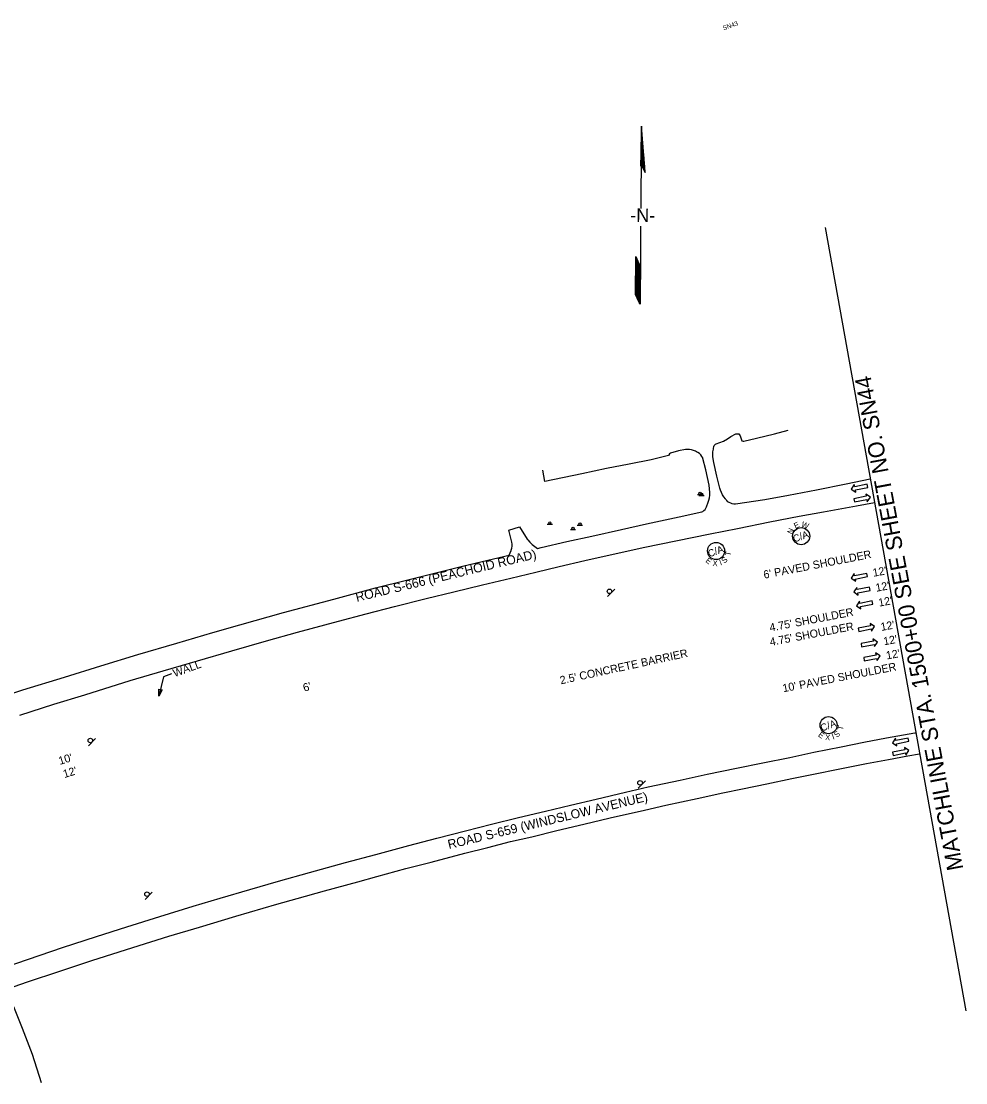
# Model space of a CAD drawing. Extents: x 1795808 to 1797487, y 1187415 to 1188757.
# Drawn here: x 1796661 to 1797487, y 1187828 to 1188757 of the extents above; entities that cross this region are included whole.
import ezdxf

# ---------------------------------------------------------------- set-up
doc = ezdxf.new("R2010")
doc.units = 0
for name, color, linetype in [('RD_EX_Road', 7, 'Continuous'), ('RD_PD_Final_LnLine', 7, 'Continuous'), ('RD_PD_Final_TX', 7, 'Continuous'), ('RD_SHT_MatchLine', 7, 'Continuous'), ('RD_SHT_TX', 7, 'Continuous'), ('RD_Sketch1', 7, 'Continuous'), ('RD_Sketch10', 7, 'Continuous'), ('RD_Sketch8', 7, 'Continuous'), ('RD_TX_RoadID', 7, 'Continuous'), ('SN_P_Signs', 7, 'Continuous')]:
    doc.layers.add(name, color=color, linetype=linetype)

# ---------------------------------------------------------------- blocks, each defined once
blk = doc.blocks.new('SARRW2')
at = {"layer": 'RD_PD_Final_LnLine'}
blk.add_lwpolyline([(-12, 1.2), (-12, -1.2), (-2.83, -1.2), (-2.83, -2.83), (0, 0), (-2.83, 2.83), (-2.83, 1.2)], close=True, dxfattribs=at)

msp = doc.modelspace()

# ---------------------------------------------------------------- linework, layer by layer
at = {"layer": 'RD_EX_Road'}
for points in [[(1797403.86, 1188356.16), (1797382.87, 1188351.83), (1797356.94, 1188346.69), (1797332.45, 1188342.01), (1797311.78, 1188338.09), (1797285.91, 1188334.36), (1797284.52, 1188334.42), (1797283.15, 1188334.67), (1797281.83, 1188335.11), (1797280.58, 1188335.73), (1797279.43, 1188336.53), (1797278.41, 1188337.47), (1797277.53, 1188338.55), (1797277.28, 1188338.93), (1797275.88, 1188340.67), (1797274.68, 1188342.55), (1797273.68, 1188344.54), (1797272.9, 1188346.63), (1797272.44, 1188348.35), (1797269.69, 1188358.97), (1797267.05, 1188370.68), (1797266.1, 1188375.63), (1797266.08, 1188377.93), (1797266.29, 1188380.22), (1797266.75, 1188382.48), (1797266.92, 1188383.13), (1797267.01, 1188384.95), (1797267.32, 1188385.72), (1797267.84, 1188386.38), (1797268.52, 1188386.87), (1797269.1, 1188387.09), (1797275.43, 1188389.41), (1797279.1, 1188391.63), (1797281.98, 1188393.65), (1797286.35, 1188395.95), (1797287.98, 1188395.96), (1797289.03, 1188395.8), (1797290.05, 1188394.26), (1797291.26, 1188390.62), (1797291.68, 1188389.67), (1797292.85, 1188389.44), (1797293.4, 1188389.41), (1797304.38, 1188392.17), (1797320.08, 1188395.84), (1797332.2, 1188399)], [(1796636.32, 1188163.25), (1796662.68, 1188171.76), (1796699.15, 1188183.11), (1796730.99, 1188192.87), (1796763.21, 1188202.7), (1796797.37, 1188212.82), (1796828.74, 1188222.07), (1796852.38, 1188228.86), (1796890.74, 1188239.52), (1796934.67, 1188251.37), (1796971.02, 1188261.03), (1796998.36, 1188267.98), (1797021.54, 1188273.83), (1797047.25, 1188280.18), (1797069.32, 1188285.35), (1797088.01, 1188289.83), (1797089.86, 1188293.89), (1797089.92, 1188294.08), (1797090.38, 1188295.82), (1797090.62, 1188297.62), (1797090.61, 1188299.43), (1797090.38, 1188301.22), (1797087.78, 1188311.57), (1797097.18, 1188314.59), (1797103.82, 1188303.7), (1797104.28, 1188303.13), (1797106.2, 1188300.98), (1797108.29, 1188299), (1797110.54, 1188297.2), (1797112.92, 1188295.59), (1797116.15, 1188296.34), (1797138.42, 1188301.69), (1797160.43, 1188306.49), (1797186.2, 1188312.28), (1797208.29, 1188317.17), (1797236.82, 1188323.27), (1797256.7, 1188327.51), (1797257.38, 1188327.92), (1797258.45, 1188328.73), (1797259.4, 1188329.69), (1797260.19, 1188330.78), (1797260.81, 1188331.98), (1797262.27, 1188336.14), (1797262.77, 1188337.77), (1797263.24, 1188340.01), (1797263.48, 1188342.3), (1797263.49, 1188344.59), (1797262.89, 1188351.09), (1797260.17, 1188364.35), (1797257.58, 1188374.28), (1797257.36, 1188374.79), (1797256.6, 1188376.18), (1797255.64, 1188377.44), (1797254.5, 1188378.55), (1797253.21, 1188379.48), (1797251.8, 1188380.2), (1797250.96, 1188380.69), (1797249.36, 1188381.42), (1797247.68, 1188381.93), (1797245.95, 1188382.2), (1797244.19, 1188382.25), (1797242.44, 1188382.05), (1797236.24, 1188381.14), (1797229.27, 1188378.84), (1797228.22, 1188378.33), (1797227.43, 1188376.81), (1797212.27, 1188373.25), (1797193.16, 1188369.45), (1797173.15, 1188365.68), (1797151.65, 1188360.89), (1797119.35, 1188354.14), (1797117.52, 1188364.24)], [(1796659.89, 1188149.79), (1796689.8, 1188159.41), (1796716.91, 1188167.63), (1796756.41, 1188179.94), (1796785.45, 1188188.57), (1796815.55, 1188197.39), (1796845.43, 1188206.1), (1796875.84, 1188214.81), (1796903.04, 1188222.38), (1796926.72, 1188228.83), (1796938.76, 1188231.95), (1796962.9, 1188238.29), (1796987.83, 1188244.85), (1797015.34, 1188251.85), (1797039.52, 1188257.66), (1797064.82, 1188263.77), (1797089.58, 1188269.64), (1797111.35, 1188274.93), (1797131.89, 1188279.71), (1797154.29, 1188284.93), (1797184.39, 1188291.71), (1797206.87, 1188296.62), (1797233.74, 1188302.2), (1797264.02, 1188308.47), (1797287.68, 1188313.18), (1797316.14, 1188318.81), (1797341.62, 1188323.8), (1797363.12, 1188327.73), (1797391.82, 1188333.03), (1797407.58, 1188335.94)], [(1796635.93, 1187925.59), (1796667.63, 1187936.38), (1796697.24, 1187946.39), (1796727.08, 1187956.16), (1796753.74, 1187964.54), (1796782.45, 1187973.61), (1796811.66, 1187982.49), (1796835.35, 1187989.64), (1796861.32, 1187997.19), (1796886.4, 1188004.48), (1796913.43, 1188012.16), (1796944.94, 1188020.91), (1796971.3, 1188027.9), (1797000.26, 1188035.74), (1797024.77, 1188042.13), (1797049.76, 1188048.54), (1797072.56, 1188054.31), (1797096.28, 1188060.16), (1797119.84, 1188065.82), (1797141.8, 1188071.08), (1797164.26, 1188076.29), (1797189.74, 1188082.28), (1797209.78, 1188086.93), (1797237.6, 1188092.96), (1797261.12, 1188097.99), (1797287.07, 1188103.41), (1797309.87, 1188108.01), (1797333.51, 1188112.78), (1797354.55, 1188117.29), (1797378.45, 1188122.13), (1797398.33, 1188126.09), (1797418.26, 1188129.77), (1797442.98, 1188134.26), (1797443.77, 1188134.4)], [(1796630.49, 1187903.95), (1796666.59, 1187916.29), (1796695.09, 1187925.83), (1796722.92, 1187934.98), (1796758.85, 1187946.48), (1796790.46, 1187956.25), (1796817.16, 1187964.28), (1796848.91, 1187973.74), (1796884.79, 1187984.4), (1796902.69, 1187989.39), (1796926.51, 1187996.16), (1796955.78, 1188003.97), (1796972.22, 1188008.55), (1796997.68, 1188015.5), (1797019.74, 1188021.14), (1797049.38, 1188028.91), (1797069.49, 1188034.04), (1797089.09, 1188039.19), (1797107.82, 1188043.4), (1797129.62, 1188048.73), (1797153.38, 1188054.48), (1797176.52, 1188059.92), (1797206.58, 1188066.75), (1797225.12, 1188070.87), (1797252.49, 1188076.84), (1797274.84, 1188081.67), (1797292.19, 1188085.42), (1797313.56, 1188089.72), (1797335.39, 1188094.26), (1797354.38, 1188098.19), (1797377.39, 1188102.8), (1797400.74, 1188107.4), (1797420, 1188111.06), (1797436.76, 1188114.07), (1797447.09, 1188115.9)], [(1796679.05, 1187828.09), (1796671.17, 1187852.73), (1796662.35, 1187875.69), (1796654.76, 1187894.64)]]:
    msp.add_lwpolyline(points, dxfattribs=at)
at = {"layer": 'RD_PD_Final_TX'}
for p, q in [((1796785.66, 1188183.37), (1796781.59, 1188166.3)), ((1796792.66, 1188185.9), (1796785.66, 1188183.37))]:
    msp.add_line(p, q, dxfattribs=at)
msp.add_lwpolyline([(1796784.44, 1188171.78), (1796781.59, 1188166.3), (1796781.52, 1188172.48)], close=True, dxfattribs=at)
at = {"layer": 'RD_SHT_MatchLine'}
msp.add_line((1797364.41, 1188576.33), (1797487.48, 1187891), dxfattribs=at)
at = {"layer": 'RD_Sketch1'}
for p, q in [((1797203.77, 1188665.17), (1797203.28, 1188630.01)), ((1797207.17, 1188624.44), (1797203.77, 1188665.17)), ((1797203.49, 1188630.3), (1797203.32, 1188608.48)), ((1797203.8, 1188631.41), (1797207.17, 1188624.44)), ((1797203.32, 1188608.48), (1797203.19, 1188593.01)), ((1797203.07, 1188577.56), (1797202.86, 1188551.79)), ((1797202.86, 1188551.79), (1797202.52, 1188509.27)), ((1797198.75, 1188536.76), (1797198.86, 1188550.93)), ((1797198.86, 1188550.93), (1797202.79, 1188542.34)), ((1797198.6, 1188517.86), (1797198.75, 1188536.76)), ((1797202.52, 1188509.27), (1797198.6, 1188517.86))]:
    msp.add_line(p, q, dxfattribs=at)
for points in [[(1797203.5, 1188630.61), (1797203.78, 1188665.05)], [(1797203.6, 1188630.87), (1797203.86, 1188664.02)], [(1797203.7, 1188631.13), (1797203.95, 1188662.98)], [(1797203.79, 1188631.39), (1797204.04, 1188661.95)], [(1797203.89, 1188631.23), (1797204.12, 1188660.92)], [(1797203.98, 1188631.04), (1797204.21, 1188659.88)], [(1797204.07, 1188630.85), (1797204.3, 1188658.85)], [(1797204.17, 1188630.66), (1797204.38, 1188657.82)], [(1797204.26, 1188630.46), (1797204.47, 1188656.78)], [(1797204.35, 1188630.27), (1797204.55, 1188655.75)], [(1797204.44, 1188630.08), (1797204.64, 1188654.72)], [(1797204.54, 1188629.89), (1797204.73, 1188653.68)], [(1797203.41, 1188630.35), (1797203.57, 1188651.13)], [(1797204.63, 1188629.69), (1797204.81, 1188652.65)], [(1797204.72, 1188629.5), (1797204.9, 1188651.62)], [(1797204.82, 1188629.31), (1797204.99, 1188650.58)], [(1797204.91, 1188629.12), (1797205.07, 1188649.55)], [(1797205, 1188628.92), (1797205.16, 1188648.52)], [(1797205.09, 1188628.73), (1797205.24, 1188647.48)], [(1797205.19, 1188628.54), (1797205.33, 1188646.45)], [(1797205.28, 1188628.35), (1797205.42, 1188645.42)], [(1797205.37, 1188628.15), (1797205.5, 1188644.38)], [(1797203.31, 1188630.09), (1797203.35, 1188635.23)], [(1797205.47, 1188627.96), (1797205.59, 1188643.35)], [(1797205.56, 1188627.77), (1797205.68, 1188642.32)], [(1797205.65, 1188627.58), (1797205.76, 1188641.28)], [(1797205.75, 1188627.38), (1797205.85, 1188640.25)], [(1797205.84, 1188627.19), (1797205.93, 1188639.22)], [(1797205.93, 1188627), (1797206.02, 1188638.18)], [(1797206.02, 1188626.81), (1797206.11, 1188637.15)], [(1797206.12, 1188626.61), (1797206.19, 1188636.12)], [(1797206.21, 1188626.42), (1797206.28, 1188635.08)], [(1797206.3, 1188626.23), (1797206.37, 1188634.05)], [(1797206.4, 1188626.04), (1797206.45, 1188633.02)], [(1797206.49, 1188625.84), (1797206.54, 1188631.99)], [(1797206.58, 1188625.65), (1797206.62, 1188630.95)], [(1797206.68, 1188625.46), (1797206.71, 1188629.92)], [(1797206.77, 1188625.27), (1797206.8, 1188628.89)], [(1797206.86, 1188625.07), (1797206.88, 1188627.85)], [(1797206.95, 1188624.88), (1797206.97, 1188626.82)], [(1797207.05, 1188624.69), (1797207.06, 1188625.79)], [(1797207.14, 1188624.5), (1797207.14, 1188624.75)], [(1797198.67, 1188517.7), (1797198.94, 1188550.77)], [(1797198.77, 1188517.5), (1797199.03, 1188550.57)], [(1797198.86, 1188517.29), (1797199.12, 1188550.36)], [(1797198.95, 1188517.09), (1797199.22, 1188550.16)], [(1797199.05, 1188516.89), (1797199.31, 1188549.96)], [(1797199.14, 1188516.68), (1797199.4, 1188549.75)], [(1797199.23, 1188516.48), (1797199.5, 1188549.55)], [(1797199.33, 1188516.28), (1797199.59, 1188549.34)], [(1797199.42, 1188516.07), (1797199.68, 1188549.14)], [(1797199.51, 1188515.87), (1797199.77, 1188548.94)], [(1797199.6, 1188515.67), (1797199.87, 1188548.73)], [(1797199.7, 1188515.46), (1797199.96, 1188548.53)], [(1797199.79, 1188515.26), (1797200.05, 1188548.33)], [(1797199.88, 1188515.06), (1797200.15, 1188548.12)], [(1797199.98, 1188514.85), (1797200.24, 1188547.92)], [(1797200.07, 1188514.65), (1797200.33, 1188547.72)], [(1797200.16, 1188514.44), (1797200.42, 1188547.51)], [(1797200.25, 1188514.24), (1797200.52, 1188547.31)], [(1797200.35, 1188514.04), (1797200.61, 1188547.11)], [(1797200.44, 1188513.83), (1797200.7, 1188546.9)], [(1797200.53, 1188513.63), (1797200.8, 1188546.7)], [(1797200.63, 1188513.43), (1797200.89, 1188546.5)], [(1797200.72, 1188513.22), (1797200.98, 1188546.29)], [(1797200.81, 1188513.02), (1797201.07, 1188546.09)], [(1797200.9, 1188512.82), (1797201.17, 1188545.89)], [(1797201, 1188512.61), (1797201.26, 1188545.68)], [(1797201.09, 1188512.41), (1797201.35, 1188545.48)], [(1797201.18, 1188512.21), (1797201.45, 1188545.28)], [(1797201.28, 1188512), (1797201.54, 1188545.07)], [(1797201.37, 1188511.8), (1797201.63, 1188544.87)], [(1797201.46, 1188511.6), (1797201.72, 1188544.67)], [(1797201.55, 1188511.39), (1797201.82, 1188544.46)], [(1797201.65, 1188511.19), (1797201.91, 1188544.26)], [(1797201.74, 1188510.99), (1797202, 1188544.06)], [(1797201.83, 1188510.78), (1797202.1, 1188543.85)], [(1797201.93, 1188510.58), (1797202.19, 1188543.65)], [(1797202.02, 1188510.38), (1797202.28, 1188543.45)], [(1797202.11, 1188510.17), (1797202.37, 1188543.24)], [(1797202.2, 1188509.97), (1797202.47, 1188543.04)], [(1797202.3, 1188509.77), (1797202.56, 1188542.84)], [(1797202.39, 1188509.56), (1797202.65, 1188542.63)], [(1797202.48, 1188509.36), (1797202.75, 1188542.43)]]:
    msp.add_lwpolyline(points, dxfattribs=at)
at = {"layer": 'RD_Sketch10'}
msp.add_circle((1797343.46, 1188306.38), 7.5, dxfattribs=at)
at = {"layer": 'RD_Sketch8'}
for centre in [(1797269.05, 1188293.41), (1797367.48, 1188140.98)]:
    msp.add_circle(centre, 7.5, dxfattribs=at)
at = {"layer": 'SN_P_Signs'}
for p, q in [((1797252.76, 1188342.74), (1797257.26, 1188342.74)), ((1797254.08, 1188341.84), (1797258.58, 1188341.84)), ((1797121.39, 1188316.95), (1797125.89, 1188316.95)), ((1797141.73, 1188312.19), (1797146.23, 1188312.19)), ((1797147.66, 1188315.97), (1797152.16, 1188315.97)), ((1797174.03, 1188253.47), (1797180.4, 1188259.84)), ((1796719.95, 1188122.97), (1796726.31, 1188129.33)), ((1797200.82, 1188085.93), (1797207.18, 1188092.3)), ((1796769.53, 1187988.52), (1796775.89, 1187994.88))]:
    msp.add_line(p, q, dxfattribs=at)
for centre, radius in [((1797255.02, 1188343.75), 1), ((1797256.34, 1188342.86), 1), ((1797123.65, 1188317.96), 1), ((1797143.99, 1188313.2), 1), ((1797149.92, 1188316.98), 1), ((1797175.79, 1188258.1), 2), ((1796721.71, 1188127.6), 2), ((1797202.58, 1188090.56), 2), ((1796771.29, 1187993.15), 2)]:
    msp.add_circle(centre, radius, dxfattribs=at)

# ---------------------------------------------------------------- block references
at = {"layer": 'RD_PD_Final_LnLine'}
for p, xscale, yscale, rotation in [((1797387.31, 1188347.6), 1.1999999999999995, 1.2000000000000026, -168.91826744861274), ((1797404.05, 1188340.46), 1.1999999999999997, 1.2000000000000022, 11.081732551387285), ((1797387.21, 1188269.61), 1.1999999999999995, 1.2000000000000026, -168.91826744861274), ((1797389.5, 1188257.54), 1.1999999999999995, 1.2000000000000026, -168.91826744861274), ((1797391.8, 1188245.47), 1.1999999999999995, 1.2000000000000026, -168.91826744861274), ((1797407.7, 1188227.25), 1.1999999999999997, 1.2000000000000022, 11.081732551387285), ((1797410.27, 1188213.72), 1.1999999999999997, 1.2000000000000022, 11.081732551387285), ((1797412.59, 1188201.52), 1.1999999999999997, 1.2000000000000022, 11.081732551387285), ((1797423.25, 1188125.52), 1.1999999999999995, 1.2000000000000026, -168.91826744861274), ((1797437.82, 1188118.76), 1.1999999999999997, 1.2000000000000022, 11.081732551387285)]:
    msp.add_blockref('SARRW2', p, dxfattribs=dict(at, xscale=xscale, yscale=yscale, rotation=rotation))

# ---------------------------------------------------------------- texts
at = {"layer": 'RD_PD_Final_TX'}
for s, rotation, p in [("6' PAVED SHOULDER", 10.96783, (1797311.18, 1188269.11)), ("12'", 10.45491, (1797406.71, 1188270.8)), ("12'", 10.37727, (1797409.21, 1188257.69)), ("12'", 10.45491, (1797411.68, 1188244.65)), ("4.75' SHOULDER", 10.84786, (1797316.46, 1188222.84)), ("4.75' SHOULDER", 10.84786, (1797316.67, 1188210.29)), ("12'", 10.37727, (1797413.65, 1188223.4)), ("12'", 10.37727, (1797416.04, 1188210.83)), ("2.5' CONCRETE BARRIER", 12.24621, (1797133.26, 1188176.68)), ("12'", 10.37727, (1797418.4, 1188198.41)), ('WALL', 19.88568, (1796795.42, 1188182.94)), ("10' PAVED SHOULDER", 10.96783, (1797327.89, 1188169.74)), ("6'", 16.97994, (1796908.92, 1188170.13)), ("10'", 16.97994, (1796695.03, 1188106.2)), ("12'", 16.97994, (1796698.97, 1188094.68))]:
    msp.add_text(s, height=7, rotation=rotation, dxfattribs=at).set_placement(p)
at = {"layer": 'RD_SHT_TX'}
for s, height, rotation, p in [('SN43', 4, 19.88568, (1797275.72, 1188748.86)), ('MATCHLINE STA. 1500+00 SEE SHEET NO. SN44', 14.1726, 100.65513, (1797485.4, 1188015.24))]:
    msp.add_text(s, height=height, rotation=rotation, dxfattribs=at).set_placement(p)
at = {"layer": 'RD_Sketch1'}
msp.add_text('-N-', height=11.811, rotation=359.54288, dxfattribs=at).set_placement((1797193.9, 1188581.34))
at = {"layer": 'RD_Sketch10'}
for s, height, rotation, p in [('W', 5, 339.18829, (1797343.22, 1188314.75)), ('N', 5, 64.75544, (1797335.45, 1188307.56)), ('C/A', 6.25, 19.88568, (1797337.6, 1188300.77)), ('E', 5, 24.21873, (1797338.43, 1188312.75))]:
    msp.add_text(s, height=height, rotation=rotation, dxfattribs=at).set_placement(p)
at = {"layer": 'RD_Sketch8'}
for s, height, rotation, p in [('C/A', 6.25, 19.88568, (1797263.19, 1188287.81)), ('T', 5, 78.07082, (1797281.59, 1188288.69)), ('E', 5, 323.09692, (1797259.43, 1188284.06)), ('X', 5, 355.52629, (1797265.85, 1188280.37)), ('I', 5, 19.68629, (1797272.93, 1188280.73)), ('S', 5, 41.67812, (1797276.31, 1188282.14)), ('C/A', 6.25, 19.88568, (1797361.63, 1188135.38)), ('E', 5, 323.09692, (1797357.87, 1188131.63)), ('I', 5, 19.68629, (1797371.37, 1188128.3)), ('S', 5, 41.67812, (1797374.75, 1188129.71)), ('T', 5, 78.07082, (1797380.03, 1188136.26)), ('X', 5, 355.52629, (1797364.29, 1188127.94))]:
    msp.add_text(s, height=height, rotation=rotation, dxfattribs=at).set_placement(p)
at = {"layer": 'RD_TX_RoadID'}
for s, p in [('ROAD S-666 (PEACHOID ROAD)', (1796954.8, 1188248.87)), ('ROAD S-659 (WINDSLOW AVENUE)', (1797035.42, 1188032.54))]:
    msp.add_text(s, height=8, rotation=13.62061, dxfattribs=at).set_placement(p)

doc.saveas('drawing.dxf')
